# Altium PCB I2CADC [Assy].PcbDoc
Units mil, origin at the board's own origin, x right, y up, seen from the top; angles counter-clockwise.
Board outline 1475 x 800 mil, 2 copper layers (Top Layer, Bottom Layer), stack 61.855 mil thick; 0 components, 9 nets, 0 pads, 0 vias.
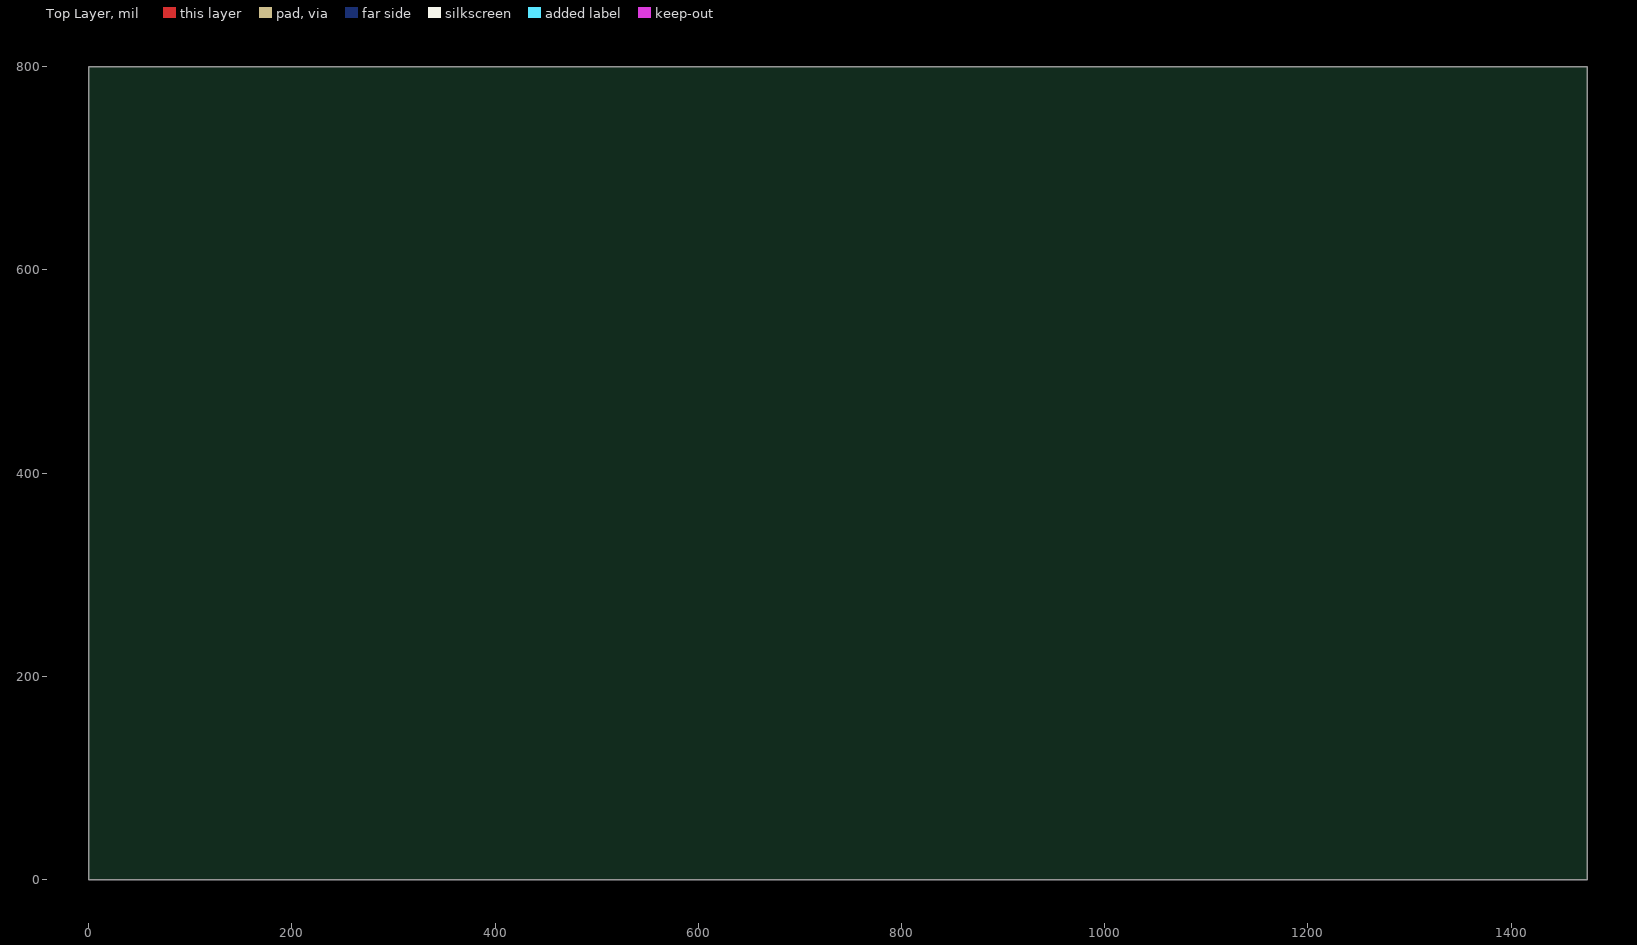
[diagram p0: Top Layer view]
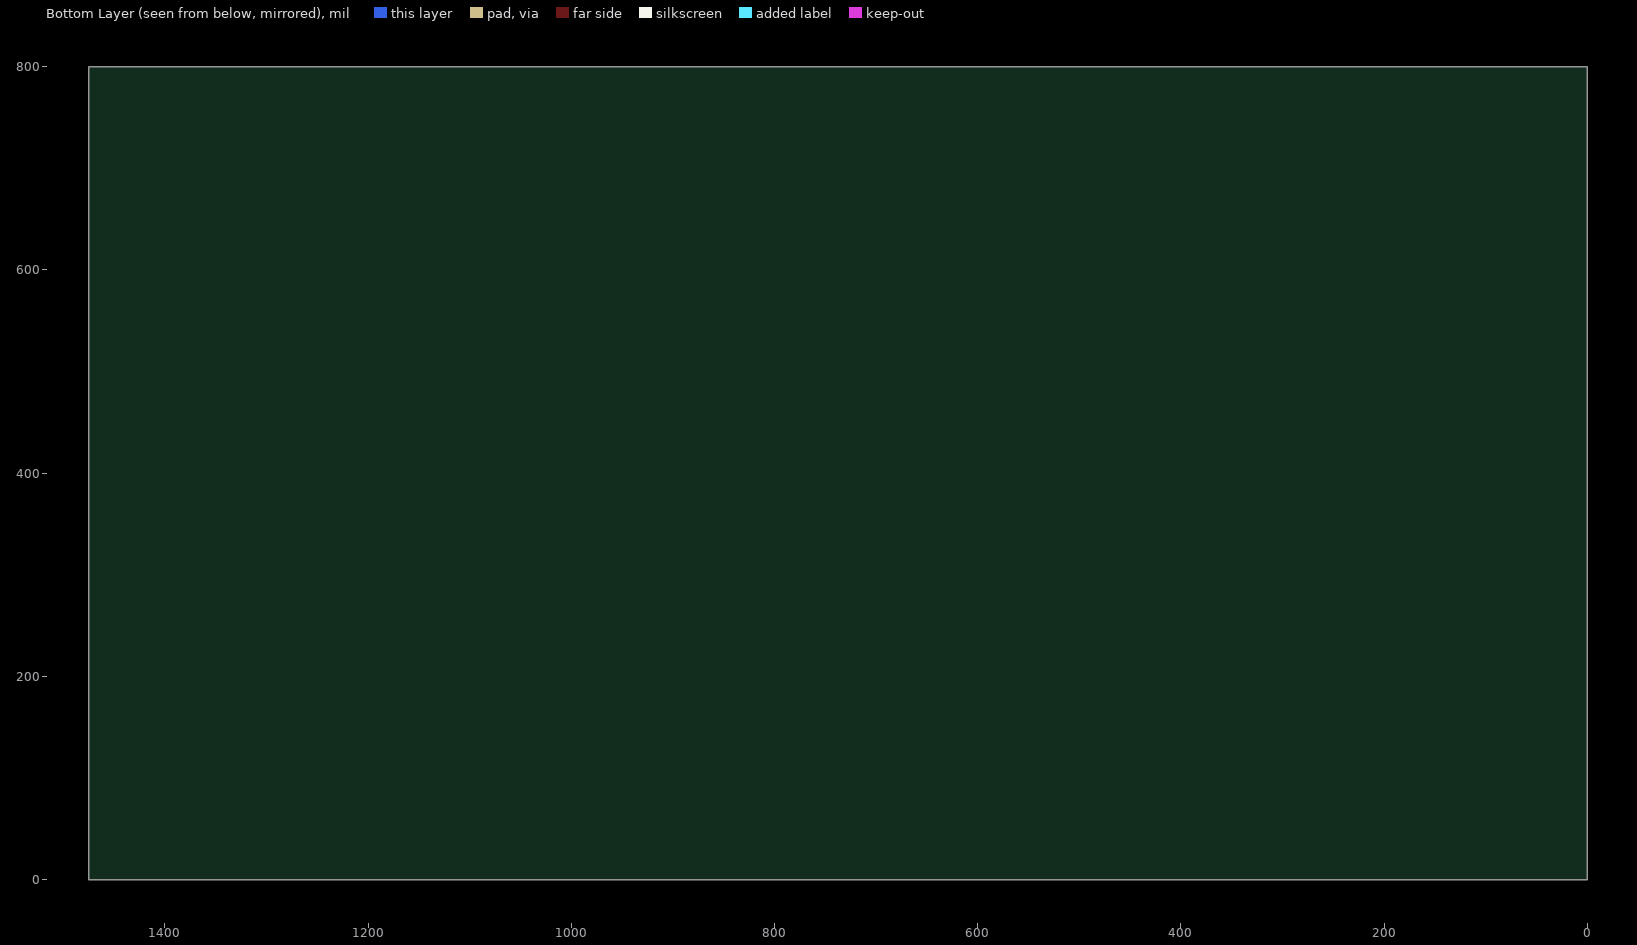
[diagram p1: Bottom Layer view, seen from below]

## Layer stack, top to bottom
Top Layer: signal copper 1.4
Dielectric: prepreg 59.0551, FR-4, Dk 4.2
Bottom Layer: signal copper 1.4

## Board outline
0,0 0,800 1475,800 1475,0

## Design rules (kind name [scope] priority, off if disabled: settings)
Clearance [All] p1: gap=6.69
FabricationTestPointUsage TestPointUsage [All] p1: valid=0 allowmultiple=FALSE
FabricationTestpoint Testpoint [All] p1: side=3 testpointundercomponent=TRUE minsize=40 maxsize=100 preferedsize=60 minholesize=0 maxholesize=40 preferedholesize=32 testpointgrid=1 allowsidetop=TRUE allowsidebottom=TRUE usegrid=TRUE gridtolerance=0.01
HoleSize [All] p1: absolutevalues=TRUE maxlimit=196.85 minlimit=9.84 maxpercent=80.000 minpercent=20.000
PlaneClearance [All] p1: clearance=19.68
PolygonConnect PolygonConnectVia [All vs isvia] p1: connectstyle=Direct reliefconductorwidth=9.84 reliefentries=4 polygonreliefangle="90 Angle" airgapwidth=10
PolygonConnect [All] p2: connectstyle=Relief reliefconductorwidth=15.75 reliefentries=4 polygonreliefangle="90 Angle" airgapwidth=10
RoutingCorners [All] p1: cornerstyle=45-Degree minsetback=98.43 maxsetback=98.43
RoutingVias [All] p1: holewidth=11.81 width=27.56 viastyle="Through Hole" minholewidth=11.81 minwidth=27.56 maxholewidth=11.81 maxwidth=27.56
SilkToSolderMaskClearance SilkscreenOverComponentPads [IsPad] p1: minsilkscreentomaskgap=10 clearancetoexposedcopper=TRUE
SolderMaskExpansion [All] p1: expansion=1.97
Width "Width_High Power" [InNetClass('High Power')] p1: maxlimit=59.06 minlimit=19.68 preferedwidth=39.37
Width Width_Power [InNetClass('Power')] p2: maxlimit=39.37 minlimit=11.81 preferedwidth=19.68
Width [All] p3: maxlimit=78.74 minlimit=7.87 preferedwidth=7.87
22 further rules are at their usual default settings.

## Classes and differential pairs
component class I2CADC: J1 J2 J3 R1 R2 R3 R4 R5 U1

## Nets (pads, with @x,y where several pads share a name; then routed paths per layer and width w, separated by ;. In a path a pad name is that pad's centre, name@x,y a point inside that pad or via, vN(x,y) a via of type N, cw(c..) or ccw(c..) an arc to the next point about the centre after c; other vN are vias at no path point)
GND: 
NetC1_1: 
NetC2_1: 
NetJ1_2: 
NetJ1_3: 
NetJ1_4: 
NetJ3_2: 
NetR4_2: 
VCC: 

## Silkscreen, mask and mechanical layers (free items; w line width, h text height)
Top Assy 1:
  circle w4.92: c0,0 r78.74
  lines w7.87: -3863.78,-1933.19 -1619.69,-1933.19 ; -3371.65,-2130.04 -3371.65,-1933.19 ; -1619.69,-1736.34 2159.84,-1736.34 5742.52,-1736.34 ; -1619.69,-1539.49 2159.84,-1539.49 ; -1619.69,-1342.64 2159.84,-1342.64 ; -1619.69,-1145.79 2159.84,-1145.79 ; -989.76,-2130.04 -989.76,-948.94 ; -590.55,393.7 -511.81,393.7 ; -590.55,787.4 -511.81,787.4 ; -511.81,0 -590.55,0 -590.55,1181.1 -511.81,1181.1 ; -359.84,-948.94 -359.84,-2130.04 -359.84,-1933.19 ; -118.11,0 -39.37,0 ; 0,-511.81 0,-590.55 1574.8,-590.55 1574.8,-511.81 ; 0,-118.11 0,-39.37 ; 270.08,-2130.04 270.08,-948.94 ; 393.7,-590.55 393.7,-511.81 ; 787.4,-590.55 787.4,-511.81 ; 900,-2130.04 900,-948.94 ; 1181.1,-590.55 1181.1,-511.81 ; 1529.92,-2130.04 1529.92,-948.94 ; 2868.5,-2130.04 2868.5,-1736.34 ; 4364.57,-2130.04 4364.57,-1736.34 ; 4876.38,-2130.04 4876.38,-1736.34 ; 5742.52,-1933.19 2159.84,-1933.19 1529.92,-1933.19 900,-1933.19 270.08,-1933.19 -359.84,-1933.19 ; -1619.69,-2130.04 -1619.69,-1933.19 ; -1619.69,-2130.04 -1619.69,-1933.19 ; -1619.69,-2130.04 -1619.69,-1933.19 ; -1619.69,-1933.19 -989.76,-1933.19 -359.84,-1933.19 ; -1619.69,-1933.19 -1619.69,-948.94 ; -1619.69,-948.94 2159.84,-948.94 ; -1619.69,-948.94 -2249.61,-948.94 -3863.78,-948.94 -3863.78,-2130.04 2159.84,-2130.04 ; 2159.84,-2130.04 5742.52,-2130.04 5742.52,-948.94 2159.84,-948.94 ; 2159.84,-2130.04 2159.84,-948.94
  text "30" at -472.44,1141.73 h98.43
  text "20" at -472.44,748.03 h98.43
  text "10" at -472.44,354.33 h98.43
  text "0" at -472.44,-39.37 h98.43
  text "0" at 39.37,-472.44 h98.43 r90
  text "10" at 433.07,-472.44 h98.43 r90
  text "20" at 826.77,-472.44 h98.43 r90
  text "30" at 1220.47,-472.44 h98.43 r90
  text "40" at 1614.17,-472.44 h98.43 r90
  text "TITLE" at 2238.58,-1067.05 h98.43
  text "AGRIGEL" at -3696.32,-1319.96 h393.7
  text ".PCB_TITLE" at 2356.69,-1382.01 h196.85
  text "TOP SIDE PLACEMENT" at 2356.69,-1539.49 h98.43
  text ".PCB_Drawn" at -1462.2,-1854.45 h98.43
  text ".PCB_Checked" at -871.65,-1854.45 h98.43
  text ".PCB_Approved" at -241.73,-1854.45 h98.43
  text ".PRINT_DATE" at 388.19,-1854.45 h98.43
  text ".PCB_DocRevision" at 939.37,-1854.45 h98.43
  text ".PCB_ECRNo" at 1687.4,-1854.45 h98.43
  text "DWG NUMBER" at 2199.21,-1854.45 h98.43
  text ".PCB_Drawing Number" at 2947.24,-1854.45 h98.43
  text "PCB VER" at 4403.94,-1854.45 h98.43
  text "SHEET NO." at 4955.12,-1854.45 h98.43
  text "PLOTFILE" at -3824.41,-2051.3 h98.43
  text ".PCB_Plot File [Assy]" at -3332.28,-2051.3 h98.43
  text "DRAWN" at -1462.2,-2051.3 h98.43
  text "CHECKED" at -871.65,-2051.3 h98.43
  text "APPROVED" at -281.1,-2051.3 h98.43
  text "DATE" at 466.93,-2051.3 h98.43
  text "DOC REV." at 1018.11,-2051.3 h98.43
  text "ECR NO." at 1687.4,-2051.3 h98.43
  text "SOURCE" at 2199.21,-2051.3 h98.43
  text ".Pcb_File_Name_No_Path" at 2947.24,-2051.3 h98.43
  text ".Version" at 4482.68,-2051.3 h98.43
  text "SHEET" at 4955.12,-2051.3 h98.43
  text "1" at 5309.45,-2051.3 h98.43
  text "OF" at 5427.56,-2051.3 h98.43
  text "2" at 5624.41,-2051.3 h98.43
Bot Assy 1:
  circle w4.92: c0,0 r78.74
  lines w7.87: -3863.78,-1933.19 -281.1,-1933.19 348.82,-1933.19 978.74,-1933.19 1608.66,-1933.19 2238.58,-1933.19 ; -3863.78,-1736.34 -281.1,-1736.34 3498.43,-1736.34 ; -2997.64,-2130.04 -2997.64,-1736.34 ; -2485.83,-2130.04 -2485.83,-1736.34 ; -989.76,-2130.04 -989.76,-1736.34 ; -590.55,393.7 -511.81,393.7 ; -590.55,787.4 -511.81,787.4 ; -511.81,0 -590.55,0 -590.55,1181.1 -511.81,1181.1 ; -281.1,-1539.49 3498.43,-1539.49 ; -281.1,-1342.64 3498.43,-1342.64 ; -281.1,-1145.79 3498.43,-1145.79 ; -118.11,0 -39.37,0 ; 0,-511.81 0,-590.55 1574.8,-590.55 1574.8,-511.81 ; 0,-118.11 0,-39.37 ; 348.82,-2130.04 348.82,-948.94 ; 393.7,-590.55 393.7,-511.81 ; 787.4,-590.55 787.4,-511.81 ; 978.74,-2130.04 978.74,-948.94 ; 1181.1,-590.55 1181.1,-511.81 ; 1608.66,-2130.04 1608.66,-948.94 ; 2238.58,-948.94 2238.58,-2130.04 2238.58,-1933.19 ; 2868.5,-2130.04 2868.5,-948.94 ; 5250.39,-2130.04 5250.39,-1933.19 ; 5742.52,-1933.19 3498.43,-1933.19 ; -281.1,-2130.04 5742.52,-2130.04 5742.52,-948.94 4128.35,-948.94 3498.43,-948.94 ; -281.1,-2130.04 -281.1,-948.94 ; -281.1,-2130.04 -3863.78,-2130.04 -3863.78,-948.94 -281.1,-948.94 ; -281.1,-948.94 3498.43,-948.94 ; 2238.58,-1933.19 2868.5,-1933.19 3498.43,-1933.19 ; 3498.43,-2130.04 3498.43,-1933.19 ; 3498.43,-2130.04 3498.43,-1933.19 ; 3498.43,-2130.04 3498.43,-1933.19 ; 3498.43,-1933.19 3498.43,-948.94
  text "30" at -372.44,1141.73 h98.43
  text "20" at -372.44,748.03 h98.43
  text "10" at -372.44,354.33 h98.43
  text "0" at -425,-39.37 h98.43
  text "10" at 433.07,-378.07 h98.43 r90
  text "20" at 826.77,-378.07 h98.43 r90
  text "30" at 1220.47,-378.07 h98.43 r90
  text "40" at 1614.17,-378.07 h98.43 r90
  text "0" at 39.96,-426.31 h98.43 r90
  text "TITLE" at -359.84,-1067.05 h98.43
  text "AGRIGEL" at 5575.06,-1319.96 h393.7
  text ".PCB_TITLE" at -477.95,-1382.01 h196.85
  text "BOTTOM SIDE PLACEMENT" at -477.95,-1539.49 h98.43
  text "SHEET NO." at -3076.38,-1854.45 h98.43
  text "PCB VER" at -2525.2,-1854.45 h98.43
  text ".PCB_Drawing Number" at -1068.5,-1854.45 h98.43
  text "DWG NUMBER" at -320.47,-1854.45 h98.43
  text ".PCB_ECRNo" at 191.34,-1854.45 h98.43
  text ".PCB_DocRevision" at 939.37,-1854.45 h98.43
  text ".PRINT_DATE" at 1490.55,-1854.45 h98.43
  text ".PCB_Approved" at 2120.47,-1854.45 h98.43
  text ".PCB_Checked" at 2750.39,-1854.45 h98.43
  text ".PCB_Drawn" at 3340.94,-1854.45 h98.43
  text "2" at -3745.67,-2051.3 h98.43
  text "OF" at -3548.82,-2051.3 h98.43
  text "2" at -3430.71,-2051.3 h98.43
  text "SHEET" at -3076.38,-2051.3 h98.43
  text ".Version" at -2603.94,-2051.3 h98.43
  text ".Pcb_File_Name_No_Path" at -1068.5,-2051.3 h98.43
  text "SOURCE" at -320.47,-2051.3 h98.43
  text "ECR NO." at 191.34,-2051.3 h98.43
  text "DOC REV." at 860.63,-2051.3 h98.43
  text "DATE" at 1411.81,-2051.3 h98.43
  text "APPROVED" at 2159.84,-2051.3 h98.43
  text "CHECKED" at 2750.39,-2051.3 h98.43
  text "DRAWN" at 3340.94,-2051.3 h98.43
  text ".PCB_Plot File [Assy]" at 5211.02,-2051.3 h98.43
  text "PLOTFILE" at 5703.15,-2051.3 h98.43

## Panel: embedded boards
"I2CADC.PcbDoc" at 0,0, 1 rows x 1 columns, spacing 2500 x 1500, rotation 0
